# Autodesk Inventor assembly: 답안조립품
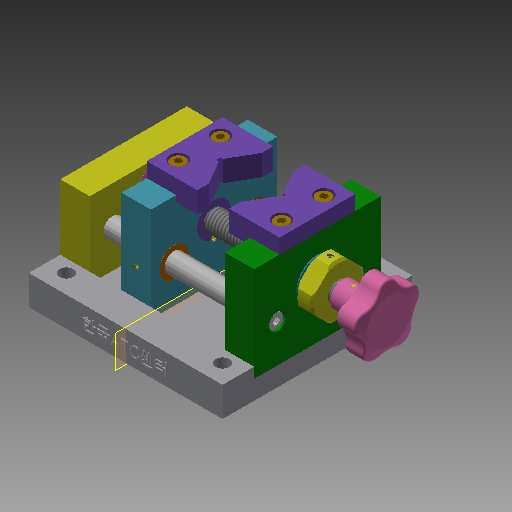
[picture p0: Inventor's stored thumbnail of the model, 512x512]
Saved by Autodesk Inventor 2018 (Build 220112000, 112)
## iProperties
Created: 2020-04
Part Number: 답안조립품
Document SubType Name: Assembly
Designer: Administrator
Author: Administrator
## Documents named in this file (19)
- C:\Users\Administrator\Desktop\600407V1033\답안조립품.iam
- C:\Users\Administrator\Desktop\600407V1033\베이스.ipt
- C:\Users\Administrator\Desktop\600407V1033\고정 조.ipt
- C:\Users\Administrator\Desktop\600407V1033\이동 조.ipt
- C:\Users\Administrator\Desktop\600407V1033\서포트.ipt
- C:\Users\Administrator\Desktop\600407V1033\부시3.ipt
- C:\Users\Administrator\Desktop\600407V1033\부시1.ipt
- C:\Users\Administrator\Desktop\600407V1033\V블럭.ipt
- C:\Users\Administrator\Desktop\600407V1033\리드스크류.ipt
- C:\Users\Administrator\Desktop\600407V1033\부시너트.ipt
- C:\Users\Administrator\Desktop\600407V1033\멈춤나사 원추점 M3 x 5.ipt
- C:\Users\Administrator\Desktop\600407V1033\멈춤나사 납작점 M3 x 6.ipt
- C:\Users\Administrator\Desktop\600407V1033\부시2.ipt
- C:\Users\Administrator\Desktop\600407V1033\슬라이딩축.ipt
- C:\Users\Administrator\Desktop\600407V1033\볼트 M4 x 10.ipt
- C:\Users\Administrator\Desktop\600407V1033\너트.ipt
- C:\Users\Administrator\Desktop\600407V1033\손잡이.ipt
- C:\Users\Administrator\Desktop\600407V1033\핀 2 x 12.ipt
- C:\Users\Administrator\Desktop\600407V1033\볼트 M4 x 8.ipt
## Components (4 placed, 3 different names)
1. 고정 조:1 — 각도:6, 각도:7
2. V블럭:1
3. V블럭:2 — 각도:3
4. 핀 2 x 12:1
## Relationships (3: Angle 3)
- 각도:3 [Angle]: V블럭:2
- 각도:6 [Angle]: 고정 조:1
- 각도:7 [Angle]: 고정 조:1
